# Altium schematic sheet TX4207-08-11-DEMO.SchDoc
size A3; Author: 周跃鸿; CompanyName: 深圳市芯鼎盛技术有限公司; SheetNumber: A
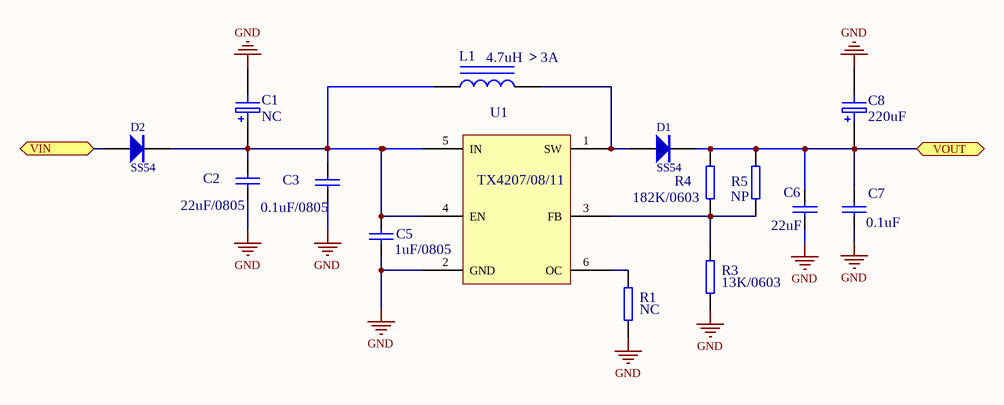
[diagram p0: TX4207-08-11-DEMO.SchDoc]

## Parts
C1  NC  [C10*16]
C2  22uF/0805  [C0805]
C3  0.1uF/0805  [C0805]
C5  1uF/0805  [C0805]
C6  22uF  [C0805]
C7  0.1uF  [C0805]
C8  220uF  [C10*16]
D1  SS54  [D-1206]
D2  SS54  [D-1206]
L1  4.7uH ＞3A  [L3015]
R1  NC  [R0402]
R3  13K/0603  [R0402]
R4  182K/0603  [R0402]
R5  NP  [R0402]
U1  TX4207/08/11  [SOT23-6]

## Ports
VIN, VOUT (bidir)

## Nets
GND: C1.2 C2.2 C3.2 C5.2 C6.2 C7.2 C8.2 R1.1 R3.1 U1.2(GND)
VIN: D2.1 ; port VIN
VOUT: C6.1 C7.1 C8.1 D1.2 R4.2 R5.2 ; port VOUT
NetC1_1: C1.1 C2.1 C3.1 C5.1 D2.2 L1.1 U1.4(EN) U1.5(IN)
NetD1_1: D1.1 L1.2 U1.1(SW)
NetR1_2: R1.2 U1.6(OC)
NetR3_2: R3.2 R4.1 R5.1 U1.3(FB)

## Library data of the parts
C1 C8 = ELECTRO1: Electrolytic Capacitor
C2 C3 C5-C7 = CAP: Capacitor
D1 D2 = SS34
L1 = L
R1 R3-R5 = R: R?
U1 = TX4208D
